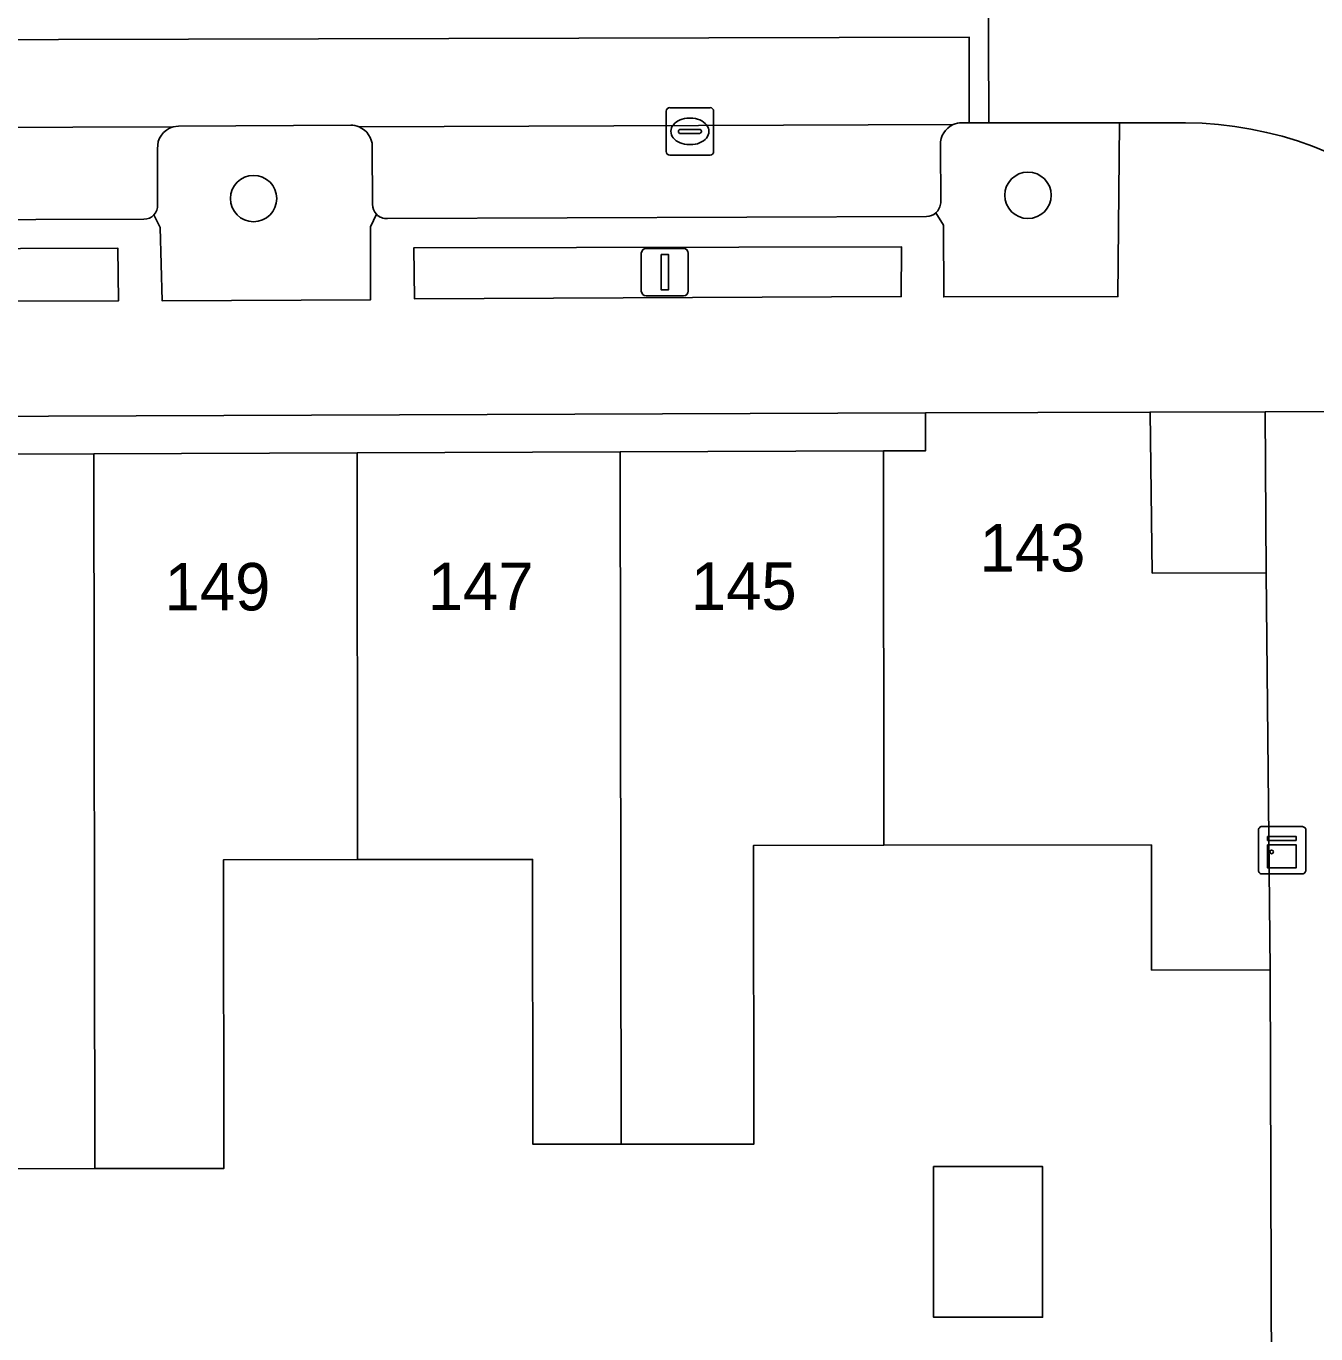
# Model space of a CAD drawing. Extents: x 159716 to 160783, y 383290 to 384031.
# Drawn here: x 160111.85 to 160139.05, y 383727.08 to 383754.67 of the extents above; entities that cross this region are included whole.
import ezdxf

# ---------------------------------------------------------------- set-up
doc = ezdxf.new("R2010")
doc.units = 0
for name, color, linetype in [('IMGEO_Boom', 7, 'Continuous'), ('IMGEO_Erf', 7, 'Continuous'), ('IMGEO_Groenvoorziening', 7, 'Continuous'), ('IMGEO_Kast', 7, 'Continuous'), ('IMGEO_Kolk', 7, 'Continuous'), ('IMGEO_Lichtmast', 7, 'Continuous'), ('IMGEO_Muur', 7, 'Continuous'), ('IMGEO_Pand', 7, 'Continuous'), ('IMGEO_Pand_nummerreeks', 7, 'Continuous'), ('IMGEO_Parkeervlak_open', 7, 'Continuous'), ('IMGEO_Rijbaan_lokaal_gesloten', 7, 'Continuous'), ('IMGEO_Rijbaan_lokaal_open', 7, 'Continuous'), ('IMGEO_Voetpad_open', 7, 'Continuous')]:
    doc.layers.add(name, color=color, linetype=linetype)

msp = doc.modelspace()

# ---------------------------------------------------------------- linework, layer by layer
at = {"layer": 'IMGEO_Boom'}
for centre in [(160116.648, 383751.029), (160132.978, 383751.098)]:
    msp.add_circle(centre, 0.489, dxfattribs=at)
at = {"layer": 'IMGEO_Erf'}
for points in [[(160137.981, 383746.534), (160135.553, 383746.525), (160135.598, 383743.13), (160137.999, 383743.132)], [(160130.817, 383746.508), (160084.576, 383746.335), (160084.578, 383745.535), (160085.54, 383745.538), (160091.088, 383745.559), (160096.637, 383745.58), (160102.185, 383745.601), (160107.734, 383745.622), (160113.282, 383745.643), (160118.831, 383745.663), (160124.379, 383745.684), (160129.928, 383745.705), (160130.82, 383745.708)], [(160133.286, 383730.612), (160133.286, 383727.432), (160130.986, 383727.432), (160130.986, 383730.612)]]:
    msp.add_lwpolyline(points, close=True, dxfattribs=at)
msp.add_lwpolyline([(160109.038, 383714.94), (160119.579, 383725.756), (160121.448, 383725.756), (160134.566, 383725.756), (160138.011, 383725.77), (160138.112, 383725.77), (160138.111, 383726.029), (160138.082, 383734.758), (160135.583, 383734.755), (160135.58, 383737.395), (160129.938, 383737.388), (160127.191, 383737.384), (160127.2, 383731.085), (160124.397, 383731.082), (160122.538, 383731.08), (160122.531, 383737.09), (160118.841, 383737.085), (160116.014, 383737.082), (160116.021, 383730.573), (160113.3, 383730.57), (160110.431, 383730.566)], dxfattribs=at)
at = {"layer": 'IMGEO_Groenvoorziening'}
for points in [[(160131.032, 383750.726), (160131.193, 383750.469), (160131.2, 383748.956), (160134.876, 383748.961), (160134.909, 383752.626)], [(160134.909, 383752.626), (160132.15, 383752.627), (160131.735, 383752.627), (160131.584, 383752.627)], [(160118.696, 383752.576), (160115.063, 383752.554), (160114.948, 383752.54)], [(160114.624, 383752.079), (160114.623, 383750.896)], [(160119.156, 383750.909), (160119.151, 383752.129)], [(160131.134, 383752.16), (160131.14, 383750.941)], [(160114.546, 383750.683), (160114.677, 383750.422), (160114.719, 383748.872), (160119.116, 383748.896), (160119.11, 383750.431), (160119.238, 383750.698)]]:
    msp.add_lwpolyline(points, dxfattribs=at)
for points in [[(160113.799, 383748.872), (160113.785, 383749.982), (160103.508, 383749.948), (160103.524, 383748.855)], [(160130.307, 383748.962), (160130.309, 383750.011), (160120.028, 383749.992), (160120.042, 383748.912)]]:
    msp.add_lwpolyline(points, close=True, dxfattribs=at)
for centre, radius, start, end in [((160131.583, 383752.177), 0.45, 114.0567, 182.2218), ((160131.585, 383752.167), 0.46, 90.1795, 113.7547), ((160115.062, 383752.116), 0.439, 105.0002, 184.7992), ((160118.703, 383752.148), 0.428, 66.6528, 90.9765), ((160118.7, 383752.124), 0.451, 0.6048, 67.4148), ((160130.821, 383750.967), 0.32, 311.2416, 355.4153), ((160114.345, 383750.876), 0.279, 316.1455, 4.1044), ((160119.45, 383750.902), 0.294, 178.6023, 223.8725)]:
    msp.add_arc(centre, radius, start, end, dxfattribs=at)
at = {"layer": 'IMGEO_Kast'}
for p, q in [((160137.837, 383736.859), (160137.837, 383737.7)), ((160137.837, 383737.7), (160137.837, 383736.859)), ((160137.912, 383737.784), (160138.753, 383737.784)), ((160138.753, 383737.784), (160137.912, 383737.784)), ((160138.837, 383737.709), (160138.837, 383736.868)), ((160138.837, 383736.868), (160138.837, 383737.709)), ((160138.762, 383736.784), (160137.921, 383736.784)), ((160137.921, 383736.784), (160138.762, 383736.784))]:
    msp.add_line(p, q, dxfattribs=at)
for points in [[(160138.032, 383737.574), (160138.632, 383737.574), (160138.632, 383737.489), (160138.032, 383737.489), (160138.032, 383737.574)], [(160138.032, 383737.399), (160138.632, 383737.399), (160138.632, 383736.91), (160138.032, 383736.91), (160138.032, 383737.399)]]:
    msp.add_lwpolyline(points, dxfattribs=at)
msp.add_circle((160138.116, 383737.248), 0.0377, dxfattribs=at)
for centre, start, end in [((160137.915, 383737.706), 92.4484, 184.2845), ((160137.915, 383737.706), 92.4484, 184.2845), ((160138.759, 383737.706), 2.4484, 94.2845), ((160138.759, 383737.706), 2.4484, 94.2845), ((160138.759, 383736.862), 272.4484, 4.2845), ((160138.759, 383736.862), 272.4484, 4.2845), ((160137.915, 383736.862), 182.4484, 274.2845), ((160137.915, 383736.862), 182.4484, 274.2845)]:
    msp.add_arc(centre, 0.0779, start, end, dxfattribs=at)
at = {"layer": 'IMGEO_Kolk'}
for p, q in [((160125.348, 383752.02), (160125.348, 383752.872)), ((160125.423, 383752.946), (160126.275, 383752.946)), ((160126.349, 383752.872), (160126.349, 383752.02)), ((160125.836, 383752.726), (160125.861, 383752.726)), ((160125.607, 383752.44), (160125.607, 383752.452)), ((160126.045, 383752.403), (160125.647, 383752.403)), ((160125.65, 383752.489), (160126.048, 383752.489)), ((160126.091, 383752.452), (160126.091, 383752.44)), ((160125.859, 383752.166), (160125.834, 383752.166)), ((160126.275, 383751.946), (160125.423, 383751.946))]:
    msp.add_line(p, q, dxfattribs=at)
for points in [[(160125.348, 383752.02), (160125.348, 383752.872)], [(160125.423, 383752.946), (160126.275, 383752.946)], [(160126.349, 383752.872), (160126.349, 383752.02)], [(160126.275, 383751.946), (160125.423, 383751.946)]]:
    msp.add_lwpolyline(points, dxfattribs=at)
for centre, radius, start, end in [((160125.425, 383752.87), 0.0765, 91.552, 178.448), ((160125.425, 383752.87), 0.0765, 91.552, 178.448), ((160126.273, 383752.87), 0.0765, 1.552, 88.448), ((160126.273, 383752.87), 0.0765, 1.552, 88.448), ((160125.647, 383752.449), 0.0403, 85.8775, 175.7526), ((160125.644, 383752.439), 0.0366, 178.938, 274.7102), ((160126.048, 383752.446), 0.043, 264.8664, 352.4533), ((160126.052, 383752.451), 0.0386, 1.7309, 96.639), ((160125.425, 383752.022), 0.0765, 181.552, 268.448), ((160125.425, 383752.022), 0.0765, 181.552, 268.448), ((160126.273, 383752.022), 0.0765, 271.552, 358.448), ((160126.273, 383752.022), 0.0765, 271.552, 358.448)]:
    msp.add_arc(centre, radius, start, end, dxfattribs=at)
for centre, major_axis, ratio, start_param, end_param in [((160125.835, 383752.446), (-0.387, 0.002), 0.722429, 4.712389, 7.853982), ((160125.86, 383752.446), (-0.39, 0.002), 0.717154, 1.570796, 4.712389)]:
    msp.add_ellipse(centre, major_axis=major_axis, ratio=ratio, start_param=start_param, end_param=end_param, dxfattribs=at)
at = {"layer": 'IMGEO_Lichtmast'}
for p, q in [((160124.824, 383749.077), (160124.824, 383749.877)), ((160124.824, 383749.877), (160124.824, 383749.077)), ((160124.924, 383749.977), (160125.714, 383749.977)), ((160125.714, 383749.977), (160124.924, 383749.977)), ((160125.814, 383749.877), (160125.814, 383749.077)), ((160125.814, 383749.077), (160125.814, 383749.877)), ((160125.714, 383748.977), (160124.924, 383748.977)), ((160124.924, 383748.977), (160125.714, 383748.977))]:
    msp.add_line(p, q, dxfattribs=at)
msp.add_lwpolyline([(160125.244, 383749.852), (160125.394, 383749.852), (160125.394, 383749.102), (160125.244, 383749.102), (160125.244, 383749.852)], dxfattribs=at)
for centre, start, end in [((160124.924, 383749.877), 90, 180), ((160124.924, 383749.877), 90, 180), ((160125.714, 383749.877), 0, 90), ((160125.714, 383749.877), 360, 90), ((160124.924, 383749.077), 180, 270), ((160124.924, 383749.077), 180, 270), ((160125.714, 383749.077), 270, 0), ((160125.714, 383749.077), 270, 0)]:
    msp.add_arc(centre, 0.1, start, end, dxfattribs=at)
at = {"layer": 'IMGEO_Muur'}
msp.add_lwpolyline([(160138.082, 383734.758), (160138.111, 383726.029)], dxfattribs=at)
at = {"layer": 'IMGEO_Pand'}
for points in [[(160137.999, 383743.132), (160135.598, 383743.13), (160135.553, 383746.525), (160130.817, 383746.508), (160130.82, 383745.708), (160129.928, 383745.705), (160129.938, 383737.388), (160135.58, 383737.395), (160135.583, 383734.755), (160138.082, 383734.758)], [(160129.928, 383745.705), (160124.379, 383745.684), (160124.397, 383731.082), (160127.2, 383731.085), (160127.191, 383737.384), (160129.938, 383737.388)], [(160113.282, 383745.643), (160107.734, 383745.622), (160107.745, 383737.052), (160110.423, 383737.056), (160110.431, 383730.566), (160113.3, 383730.57)], [(160118.831, 383745.663), (160113.282, 383745.643), (160113.3, 383730.57), (160116.021, 383730.573), (160116.014, 383737.082), (160118.841, 383737.085)], [(160124.379, 383745.684), (160118.831, 383745.663), (160118.841, 383737.085), (160122.531, 383737.09), (160122.538, 383731.08), (160124.397, 383731.082)], [(160133.286, 383727.432), (160133.286, 383730.612), (160130.986, 383730.612), (160130.986, 383727.432)]]:
    msp.add_lwpolyline(points, close=True, dxfattribs=at)
at = {"layer": 'IMGEO_Parkeervlak_open'}
for points in [[(160131.4, 383752.588), (160118.873, 383752.541)], [(160114.948, 383752.54), (160102.293, 383752.498)], [(160114.623, 383750.896), (160114.624, 383752.079)], [(160119.151, 383752.129), (160119.156, 383750.909)], [(160131.14, 383750.941), (160131.134, 383752.16)], [(160102.952, 383750.559), (160114.334, 383750.594)], [(160119.47, 383750.606), (160130.841, 383750.649)]]:
    msp.add_lwpolyline(points, dxfattribs=at)
for centre, radius, start, end in [((160131.583, 383752.177), 0.45, 114.0567, 182.2218), ((160115.062, 383752.116), 0.439, 105.0002, 184.7992), ((160118.7, 383752.124), 0.451, 0.6048, 67.4148), ((160130.821, 383750.967), 0.32, 311.2416, 355.4153), ((160114.339, 383750.879), 0.285, 268.9696, 316.5768), ((160114.345, 383750.876), 0.279, 316.1455, 4.1044), ((160119.45, 383750.902), 0.294, 178.6023, 223.8725), ((160119.456, 383750.908), 0.303, 224.0168, 272.7214), ((160130.822, 383750.972), 0.324, 273.4166, 310.4962)]:
    msp.add_arc(centre, radius, start, end, dxfattribs=at)
at = {"layer": 'IMGEO_Rijbaan_lokaal_gesloten'}
for points in [[(160131.584, 383752.627), (160131.735, 383752.627), (160131.736, 383754.435), (160087.833, 383754.324)], [(160118.873, 383752.541), (160131.4, 383752.588)], [(160079.852, 383752.446), (160079.914, 383752.444), (160098.634, 383752.483), (160098.745, 383752.495), (160102.201, 383752.519), (160102.293, 383752.498), (160114.948, 383752.54), (160115.063, 383752.554), (160118.696, 383752.576)]]:
    msp.add_lwpolyline(points, dxfattribs=at)
for centre, radius, start, end in [((160131.585, 383752.167), 0.46, 90.1795, 113.7547), ((160118.703, 383752.148), 0.428, 66.6528, 90.9765)]:
    msp.add_arc(centre, radius, start, end, dxfattribs=at)
at = {"layer": 'IMGEO_Rijbaan_lokaal_open'}
for points in [[(160087.833, 383754.324), (160131.736, 383754.435), (160131.735, 383752.627), (160132.15, 383752.627), (160132.147, 383754.39), (160132.143, 383756.363)], [(160132.143, 383756.363), (160132.147, 383754.39), (160132.15, 383752.627), (160134.909, 383752.626), (160135.949, 383752.626)]]:
    msp.add_lwpolyline(points, dxfattribs=at)
msp.add_arc((160136.215, 383744.701), 7.929, 13.4896, 91.9203, dxfattribs=at)
at = {"layer": 'IMGEO_Voetpad_open'}
for points in [[(160135.949, 383752.626), (160134.909, 383752.626), (160134.876, 383748.961), (160131.2, 383748.956), (160131.193, 383750.469), (160131.032, 383750.726)], [(160119.238, 383750.698), (160119.11, 383750.431), (160119.116, 383748.896), (160114.719, 383748.872), (160114.677, 383750.422), (160114.546, 383750.683)], [(160114.334, 383750.594), (160102.952, 383750.559)], [(160130.841, 383750.649), (160119.47, 383750.606)], [(160052.613, 383740.552), (160053.509, 383737.802), (160054.838, 383738.238), (160073.846, 383744.362), (160073.988, 383743.935), (160076.918, 383743.972), (160077.049, 383744.402), (160077.303, 383744.324), (160077.018, 383743.115), (160077.467, 383743.109), (160077.468, 383742.909), (160079.887, 383742.919), (160079.829, 383746.321), (160084.576, 383746.335), (160130.817, 383746.508), (160135.553, 383746.525), (160137.981, 383746.534), (160143.925, 383746.551)], [(160143.925, 383746.551), (160137.981, 383746.534), (160137.999, 383743.132), (160138.082, 383734.758), (160138.111, 383726.029), (160138.112, 383725.77), (160138.116, 383724.465), (160138.133, 383722.105), (160138.151, 383718.197), (160138.155, 383717.365), (160138.214, 383706.867), (160138.221, 383705.895), (160138.247, 383702.107), (160138.197, 383698.271), (160138.246, 383695.773), (160137.338, 383694.486), (160128.261, 383691.6), (160125.089, 383690.591), (160125.22, 383690.183), (160124.416, 383689.912), (160125.17, 383687.56), (160125.399, 383685.725), (160125.665, 383684.829)]]:
    msp.add_lwpolyline(points, dxfattribs=at)
for points in [[(160103.524, 383748.855), (160103.508, 383749.948), (160113.785, 383749.982), (160113.799, 383748.872)], [(160120.028, 383749.992), (160130.309, 383750.011), (160130.307, 383748.962), (160120.042, 383748.912)]]:
    msp.add_lwpolyline(points, close=True, dxfattribs=at)
for centre, radius, start, end in [((160136.215, 383744.701), 7.929, 13.4896, 91.9203), ((160114.339, 383750.879), 0.285, 268.9696, 316.5768), ((160119.456, 383750.908), 0.303, 224.0168, 272.7214), ((160130.822, 383750.972), 0.324, 273.4166, 310.4962)]:
    msp.add_arc(centre, radius, start, end, dxfattribs=at)

# ---------------------------------------------------------------- texts
at = {"layer": 'IMGEO_Pand_nummerreeks'}
for s, rotation, p in [('143', 0.063, (160131.959, 383743.162)), ('149', 0.0688, (160114.772, 383742.34)), ('147', 0.0688, (160120.321, 383742.347)), ('145', 0.0688, (160125.869, 383742.353))]:
    msp.add_text(s, height=1, rotation=rotation, dxfattribs=at).set_placement(p)

doc.saveas('drawing.dxf')
